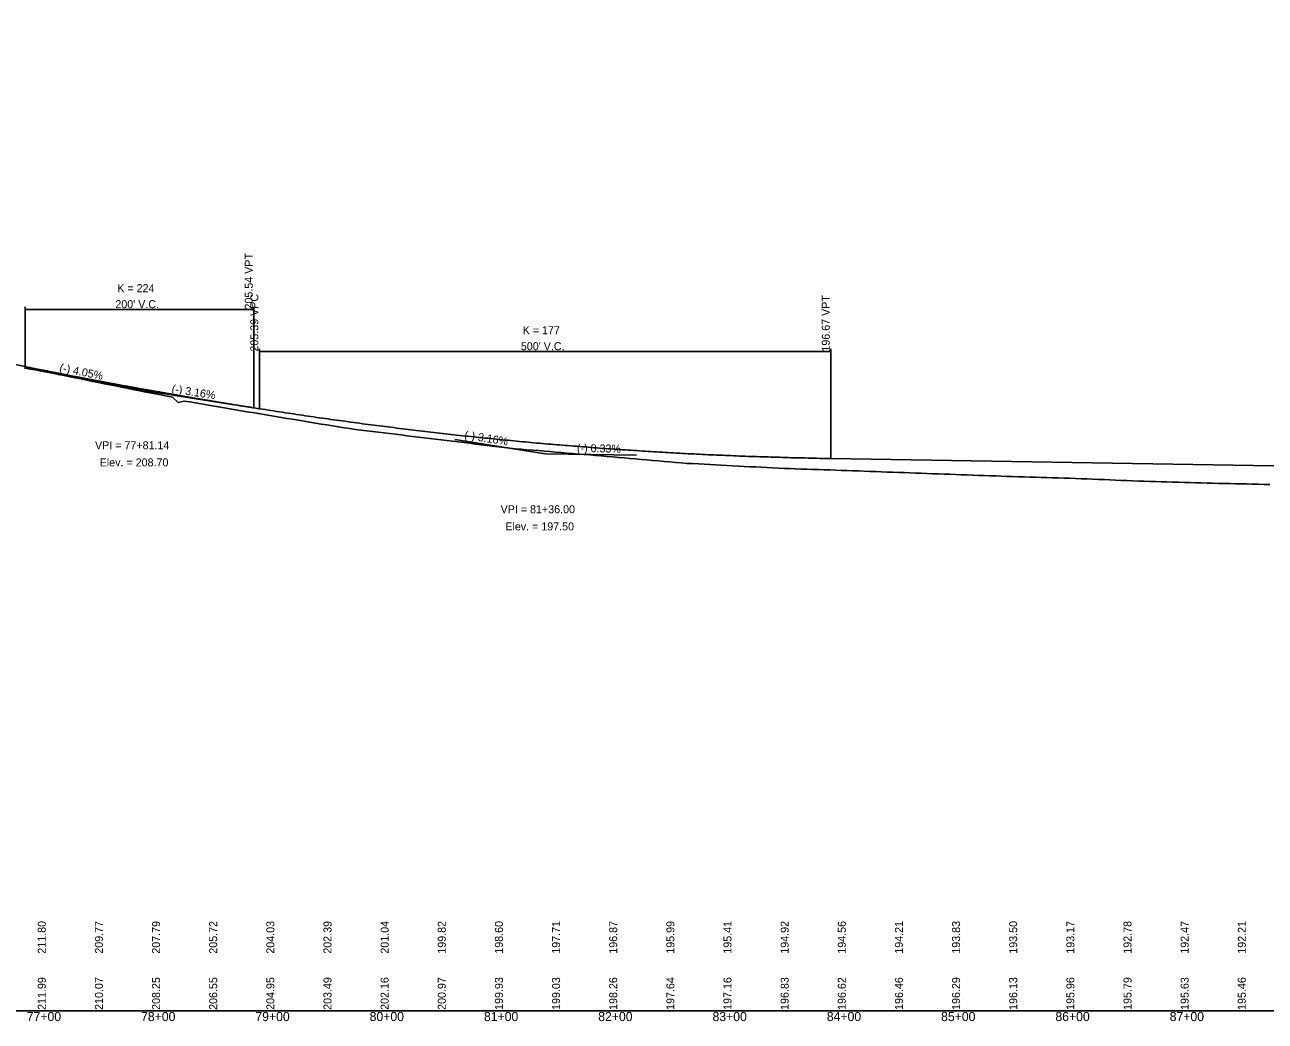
# Model space of a CAD drawing. Extents: x 1838386 to 1955906, y 719739 to 834437.
# Drawn here: x 1885044 to 1886129, y 823083 to 823955 of the extents above; entities that cross this region are included whole.
import ezdxf

# ---------------------------------------------------------------- set-up
doc = ezdxf.new("R2010")
doc.units = 0
for name, color, linetype in [('RD_DDB_GradeTX', 7, 'Continuous'), ('RD_DDB_Profile_EX', 7, 'Continuous'), ('RD_DDB_Profile_Lbl', 7, 'Continuous'), ('RD_DDB_Profile_PR', 7, 'Continuous'), ('RD_DDB_StaTX', 7, 'Continuous'), ('RD_DDB_StripGrade', 7, 'Continuous'), ('RD_DDB_VCLbl', 7, 'Continuous'), ('RD_GPK_Profile_Cell', 7, 'Continuous')]:
    doc.layers.add(name, color=color, linetype=linetype)

msp = doc.modelspace()

# ---------------------------------------------------------------- linework, layer by layer
at = {"layer": 'RD_DDB_GradeTX'}
for p, q in [((1885065.8, 823651), (1885144.2, 823635.1)), ((1885223.2, 823622.6), (1885144.2, 823635.1)), ((1885420.1, 823591.6), (1885499.1, 823579.1)), ((1885579.1, 823577.8), (1885499.1, 823579.1))]:
    msp.add_line(p, q, dxfattribs=at)
at = {"layer": 'RD_DDB_Profile_EX'}
for points in [[(1885043.1, 823654.5), (1885048.1, 823653.3), (1885053.1, 823652.5), (1885058.1, 823651.5), (1885063.1, 823650.6), (1885068.1, 823649.6), (1885073.1, 823648.5), (1885078.1, 823647.6), (1885083.1, 823646.6), (1885088.1, 823645.6), (1885093.1, 823644.7), (1885098.1, 823643.6), (1885103.1, 823642.5), (1885108.1, 823641.6), (1885113.1, 823640.5), (1885118.1, 823639.5), (1885123.1, 823638.6), (1885128.1, 823637.5), (1885133.1, 823636.5), (1885138.1, 823635.4), (1885143.1, 823634.5), (1885148.1, 823633.4), (1885153.1, 823632.5), (1885158.1, 823631.5), (1885163.1, 823630.6), (1885168.1, 823629.6), (1885173.1, 823628.6), (1885178.1, 823623.9), (1885183.1, 823625.3), (1885188.1, 823624.5), (1885193.1, 823623.6), (1885198.1, 823622.8), (1885203.1, 823621.9), (1885208.1, 823621.1), (1885213.1, 823620.2), (1885218.1, 823619.4), (1885223.1, 823618.5), (1885228.1, 823617.7), (1885233.1, 823616.8), (1885238.1, 823616), (1885243.1, 823615.2), (1885248.1, 823614.3), (1885253.1, 823613.5), (1885258.1, 823612.6), (1885263.1, 823611.8), (1885268.1, 823611), (1885273.1, 823610.1), (1885278.1, 823609.3), (1885283.1, 823608.5), (1885288.1, 823607.7), (1885293.1, 823606.8), (1885298.1, 823606), (1885303.1, 823605.2), (1885308.1, 823604.4), (1885313.1, 823603.6), (1885318.1, 823602.7), (1885323.1, 823601.9), (1885328.1, 823601.2), (1885333.1, 823600.5), (1885338.1, 823599.9), (1885343.1, 823599.3), (1885348.1, 823598.7), (1885353.1, 823598.1), (1885358.1, 823597.5), (1885363.1, 823596.8)], [(1885363.1, 823596.8), (1885368.1, 823596.2), (1885373.1, 823595.6), (1885378.1, 823595), (1885383.1, 823594.4), (1885388.1, 823593.8), (1885393.1, 823593.1), (1885398.1, 823592.5), (1885403.1, 823591.9), (1885408.1, 823591.3), (1885413.1, 823590.7), (1885418.1, 823590.1), (1885423.1, 823589.5), (1885428.1, 823588.9), (1885433.1, 823588.3), (1885438.1, 823587.7), (1885443.1, 823587.1), (1885448.1, 823586.4), (1885453.1, 823585.8), (1885458.1, 823585.2), (1885463.1, 823584.6), (1885468.1, 823584), (1885473.1, 823583.5), (1885478.1, 823583.1), (1885483.1, 823582.7), (1885488.1, 823582.3), (1885493.1, 823581.9), (1885498.1, 823581.4), (1885503.1, 823581), (1885508.1, 823580.6), (1885513.1, 823580.2), (1885518.1, 823579.8), (1885523.1, 823579.4), (1885528.1, 823578.9), (1885533.1, 823578.5), (1885538.1, 823578.1), (1885543.1, 823577.7), (1885548.1, 823577.3), (1885553.1, 823576.8), (1885558.1, 823576.4), (1885563.1, 823576), (1885568.1, 823575.5), (1885573.1, 823575.1), (1885578.1, 823574.7), (1885583.1, 823574.2), (1885588.1, 823573.8), (1885593.1, 823573.3), (1885598.1, 823572.9), (1885603.1, 823572.5), (1885608.1, 823572), (1885613.1, 823571.6), (1885618.1, 823571.1), (1885623.1, 823570.7), (1885628.1, 823570.5), (1885633.1, 823570.3), (1885638.1, 823570), (1885643.1, 823569.8), (1885648.1, 823569.5), (1885653.1, 823569.2), (1885658.1, 823569), (1885663.1, 823568.7), (1885668.1, 823568.4), (1885673.1, 823568.1), (1885678.1, 823567.8), (1885683.1, 823567.6), (1885688.1, 823567.3), (1885693.1, 823567), (1885698.1, 823566.8), (1885703.1, 823566.6), (1885708.1, 823566.4), (1885713.1, 823566.2), (1885718.1, 823566), (1885723.1, 823565.8), (1885728.1, 823565.6), (1885733.1, 823565.5), (1885738.1, 823565.3), (1885743.1, 823565.1), (1885748.1, 823565), (1885753.1, 823564.8), (1885758.1, 823564.6), (1885763.1, 823564.4), (1885768.1, 823564.3), (1885773.1, 823564.1), (1885778.1, 823563.9), (1885783.1, 823563.7), (1885788.1, 823563.6), (1885793.1, 823563.4), (1885798.1, 823563.2), (1885803.1, 823563), (1885808.1, 823562.9), (1885813.1, 823562.7), (1885818.1, 823562.5), (1885823.1, 823562.3), (1885828.1, 823562.1), (1885833.1, 823561.9), (1885838.1, 823561.7), (1885843.1, 823561.5), (1885848.1, 823561.3), (1885853.1, 823561.2), (1885858.1, 823561), (1885863.1, 823560.8)], [(1885863.1, 823560.8), (1885868.1, 823560.6), (1885873.1, 823560.4), (1885878.1, 823560.2), (1885883.1, 823560), (1885888.1, 823559.8), (1885893.1, 823559.7), (1885898.1, 823559.5), (1885903.1, 823559.4), (1885908.1, 823559.3), (1885913.1, 823559.1), (1885918.1, 823559), (1885923.1, 823558.8), (1885928.1, 823558.7), (1885933.1, 823558.5), (1885938.1, 823558.4), (1885943.1, 823558.2), (1885948.1, 823558), (1885953.1, 823557.8), (1885958.1, 823557.7), (1885963.1, 823557.5), (1885968.1, 823557.3), (1885973.1, 823557.1), (1885978.1, 823556.9), (1885983.1, 823556.7), (1885988.1, 823556.5), (1885993.1, 823556.3), (1885998.1, 823556.1), (1886003.1, 823555.9), (1886008.1, 823555.7), (1886013.1, 823555.5), (1886018.1, 823555.3), (1886023.1, 823555.2), (1886028.1, 823555), (1886033.1, 823554.9), (1886038.1, 823554.7), (1886043.1, 823554.6), (1886048.1, 823554.4), (1886053.1, 823554.3), (1886058.1, 823554.1), (1886063.1, 823554), (1886068.1, 823553.8), (1886073.1, 823553.7), (1886078.1, 823553.5), (1886083.1, 823553.4), (1886088.1, 823553.2), (1886093.1, 823553.1), (1886098.1, 823553), (1886103.1, 823552.9), (1886108.1, 823552.8), (1886113.1, 823552.7), (1886118.1, 823552.6), (1886123.1, 823552.5), (1886128.1, 823552.4), (1886133.1, 823552.3)]]:
    msp.add_lwpolyline(points, dxfattribs=at)
at = {"layer": 'RD_DDB_Profile_PR'}
for p, q in [((1883565.8, 823954.6), (1885044.2, 823655.4)), ((1885244.2, 823619.3), (1885249.1, 823618.6)), ((1885749.1, 823575), (1886308.5, 823565.7))]:
    msp.add_line(p, q, dxfattribs=at)
for points in [[(1885044.2, 823655.4), (1885048.2, 823654.6), (1885052.2, 823653.7), (1885056.2, 823652.9), (1885060.2, 823652.2), (1885064.2, 823651.4), (1885068.2, 823650.6), (1885072.2, 823649.8), (1885076.2, 823649), (1885080.2, 823648.2), (1885084.2, 823647.4), (1885088.2, 823646.7), (1885092.2, 823645.9), (1885096.2, 823645.1), (1885100.2, 823644.4), (1885104.2, 823643.6), (1885108.2, 823642.9), (1885112.2, 823642.1), (1885116.2, 823641.4), (1885120.2, 823640.6), (1885124.2, 823639.9), (1885128.2, 823639.1), (1885132.2, 823638.4), (1885136.2, 823637.7), (1885140.2, 823637), (1885144.2, 823636.2), (1885148.2, 823635.5), (1885152.2, 823634.8), (1885156.2, 823634.1), (1885160.2, 823633.4), (1885164.2, 823632.7), (1885168.2, 823632), (1885172.2, 823631.3), (1885176.2, 823630.6), (1885180.2, 823629.9), (1885184.2, 823629.2), (1885188.2, 823628.5), (1885192.2, 823627.8), (1885196.2, 823627.2), (1885200.2, 823626.5), (1885204.2, 823625.8), (1885208.2, 823625.2), (1885212.2, 823624.5), (1885216.2, 823623.8), (1885220.2, 823623.2), (1885224.2, 823622.5), (1885228.2, 823621.9), (1885232.2, 823621.2), (1885236.2, 823620.6), (1885240.2, 823620), (1885244.2, 823619.3)], [(1885249.1, 823618.6), (1885259.1, 823617), (1885269.1, 823615.5), (1885279.1, 823614), (1885289.1, 823612.5), (1885299.1, 823611), (1885309.1, 823609.6), (1885319.1, 823608.2), (1885329.1, 823606.9), (1885339.1, 823605.5), (1885349.1, 823604.2), (1885359.1, 823602.9), (1885369.1, 823601.7), (1885379.1, 823600.4), (1885389.1, 823599.2), (1885399.1, 823598.1), (1885409.1, 823596.9), (1885419.1, 823595.8), (1885429.1, 823594.7), (1885439.1, 823593.7), (1885449.1, 823592.7), (1885459.1, 823591.7), (1885469.1, 823590.7), (1885479.1, 823589.7), (1885489.1, 823588.8), (1885499.1, 823587.9), (1885509.1, 823587.1), (1885519.1, 823586.3), (1885529.1, 823585.5), (1885539.1, 823584.7), (1885549.1, 823583.9), (1885559.1, 823583.2), (1885569.1, 823582.5), (1885579.1, 823581.9), (1885589.1, 823581.2), (1885599.1, 823580.6), (1885609.1, 823580.1), (1885619.1, 823579.5), (1885629.1, 823579), (1885639.1, 823578.5), (1885649.1, 823578), (1885659.1, 823577.6), (1885669.1, 823577.2), (1885679.1, 823576.8), (1885689.1, 823576.5), (1885699.1, 823576.2), (1885709.1, 823575.9), (1885719.1, 823575.6), (1885729.1, 823575.4), (1885739.1, 823575.1), (1885749.1, 823575)]]:
    msp.add_spline(points, degree=3, dxfattribs=at)
at = {"layer": 'RD_DDB_VCLbl'}
for p, q in [((1885044.2, 823707.9), (1885044.2, 823655.4)), ((1885244.2, 823707.9), (1885244.2, 823619.3)), ((1885044.2, 823705.4), (1885244.2, 823705.4)), ((1885249.1, 823671.1), (1885249.1, 823618.6)), ((1885249.1, 823668.6), (1885749.1, 823668.6)), ((1885749.1, 823671.1), (1885749.1, 823575))]:
    msp.add_line(p, q, dxfattribs=at)
at = {"layer": 'RD_GPK_Profile_Cell'}
msp.add_line((1878363.1, 823091.6), (1904963.1, 823091.6), dxfattribs=at)

# ---------------------------------------------------------------- texts
at = {"layer": 'RD_DDB_GradeTX'}
for s, rotation, p in [('(-) 4.05%', 348.5567, (1885073.7, 823651.4)), ('(-) 3.16%', 351.0322, (1885171.9, 823632.8)), ('(-) 3.16%', 351.0322, (1885428, 823592.4)), ('(-) 0.33%', 359.0487, (1885526.8, 823580.7))]:
    msp.add_text(s, height=7, rotation=rotation, dxfattribs=at).set_placement(p)
at = {"layer": 'RD_DDB_Profile_Lbl'}
for s, p in [('VPI = 77+81.14', (1885105.2, 823583.1)), ('Elev. = 208.70', (1885109.3, 823568.1)), ('VPI = 81+36.00', (1885460.1, 823527.1)), ('Elev. = 197.50', (1885464.2, 823512.1))]:
    msp.add_text(s, height=7, dxfattribs=at).set_placement(p)
at = {"layer": 'RD_DDB_StaTX'}
for s, p in [('77+00', (1885045.5, 823082.6)), ('78+00', (1885145.5, 823082.6)), ('79+00', (1885245.5, 823082.6)), ('80+00', (1885345.5, 823082.6)), ('81+00', (1885445.5, 823082.6)), ('82+00', (1885545.5, 823082.6)), ('83+00', (1885645.5, 823082.6)), ('84+00', (1885745.5, 823082.6)), ('85+00', (1885845.5, 823082.6)), ('86+00', (1885945.5, 823082.6)), ('87+00', (1886045.5, 823082.6))]:
    msp.add_text(s, height=8, dxfattribs=at).set_placement(p)
at = {"layer": 'RD_DDB_StripGrade'}
for s, p in [('205.54 VPT', (1885243.2, 823705.4)), ('205.39 VPC', (1885248.1, 823668.6)), ('196.67 VPT', (1885748.1, 823668.6)), ('211.80', (1885062.1, 823141.6)), ('209.77', (1885112.1, 823141.6)), ('207.79', (1885162.1, 823141.6)), ('205.72', (1885212.1, 823141.6)), ('204.03', (1885262.1, 823141.6)), ('202.39', (1885312.1, 823141.6)), ('201.04', (1885362.1, 823141.6)), ('199.82', (1885412.1, 823141.6)), ('198.60', (1885462.1, 823141.6)), ('197.71', (1885512.1, 823141.6)), ('196.87', (1885562.1, 823141.6)), ('195.99', (1885612.1, 823141.6)), ('195.41', (1885662.1, 823141.6)), ('194.92', (1885712.1, 823141.6)), ('194.56', (1885762.1, 823141.6)), ('194.21', (1885812.1, 823141.6)), ('193.83', (1885862.1, 823141.6)), ('193.50', (1885912.1, 823141.6)), ('193.17', (1885962.1, 823141.6)), ('192.78', (1886012.1, 823141.6)), ('192.47', (1886062.1, 823141.6)), ('192.21', (1886112.1, 823141.6)), ('211.99', (1885062.1, 823092.4)), ('210.07', (1885112.1, 823092.4)), ('208.25', (1885162.1, 823092.4)), ('206.55', (1885212.1, 823092.4)), ('204.95', (1885262.1, 823092.4)), ('203.49', (1885312.1, 823092.4)), ('202.16', (1885362.1, 823092.4)), ('200.97', (1885412.1, 823092.4)), ('199.93', (1885462.1, 823092.4)), ('199.03', (1885512.1, 823092.4)), ('198.26', (1885562.1, 823092.4)), ('197.64', (1885612.1, 823092.4)), ('197.16', (1885662.1, 823092.4)), ('196.83', (1885712.1, 823092.4)), ('196.62', (1885762.1, 823092.4)), ('196.46', (1885812.1, 823092.4)), ('196.29', (1885862.1, 823092.4)), ('196.13', (1885912.1, 823092.4)), ('195.96', (1885962.1, 823092.4)), ('195.79', (1886012.1, 823092.4)), ('195.63', (1886062.1, 823092.4)), ('195.46', (1886112.1, 823092.4))]:
    msp.add_text(s, height=7, rotation=90, dxfattribs=at).set_placement(p)
at = {"layer": 'RD_DDB_VCLbl'}
for s, p in [('K = 224', (1885124.7, 823720.6)), ("200' V.C.", (1885123, 823706.6)), ('K = 177', (1885479.4, 823683.8)), ("500' V.C.", (1885477.8, 823669.8))]:
    msp.add_text(s, height=7, dxfattribs=at).set_placement(p)

doc.saveas('drawing.dxf')
